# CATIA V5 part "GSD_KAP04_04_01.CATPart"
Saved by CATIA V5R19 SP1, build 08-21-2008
Part number: GSD_KAP04_04_01
Definition: Beispielmodell Kapitel 4 - Sketcher
Description: CATIA V5 Flächenmodellierung  Copyright (c) 2009 Maik Hertha IT Consultants
Bounding box of the stored display mesh (mm): x -134.998 to 40, y 0 to 0, z -55 to 55
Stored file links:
  \GSD_BUCH_UEBUNG\GSD_KAP04_04_01.CATPart
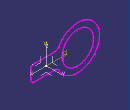
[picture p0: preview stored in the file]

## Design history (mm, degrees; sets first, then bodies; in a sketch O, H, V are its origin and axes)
AxisSystem1: origin (0, 0, 0), X (1, 0, 0), Y (0, 1, 0), Z (0, 0, 1)
Set1
  Sketch1 on zx-plane, origin (0, 0, 0), H (-1, 0, 0), V (0, 0, 1)
    point P1 (-35, 20)
    line L1 (-35, 20) -> (22.3372, 20)
    arc A1 centre (22.3372, 30) radius 10 from (22.3372, 20) to (31.2084, 25.3846) ccw
    arc A2 centre (80, 0) radius 55 from (31.2084, 25.3846) to (31.2084, -25.3846) cw
    point P5 (80, 0)
    arc A3 centre (22.3372, -30) radius 10 from (31.2084, -25.3846) to (22.3372, -20) ccw
    line L2 (22.3372, -20) -> (-30, -20)
    arc A4 centre (-30, -10) radius 10 from (-30, -20) to (-40, -10) cw
    line L3 (-40, -10) -> (-40, 15)
    line L4 (-40, 15) -> (-35, 20)
    circle A5 centre (80, 0) radius 40
    radius A2 = 55
    radius A1 = 10
    radius A3 = 10
    radius A4 = 10
    distance P5 H = 0
    distance L1 L2 = 40
    distance P5 V = 80
    distance L3 V = 40
    distance L3 P1 = 5
    angle L4 L1 = 45
    radius A5 = 40
    tangency: A1 A2, A1 L1, A3 A2, A3 L2, A4 L2, A4 L3
    symmetry: L1 L2 H
    vertical: L3 V
Body1 (main body)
